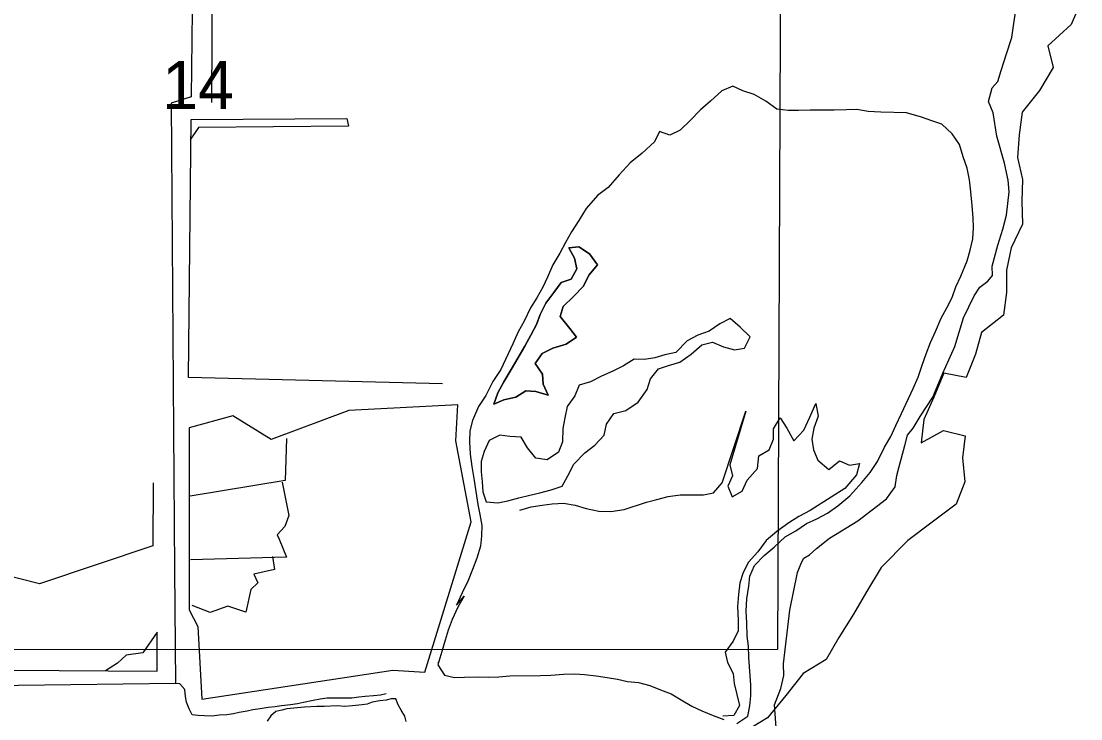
# Model space of a CAD drawing. Extents: x 0 to 34, y 0 to 22.
# Drawn here: x 2.4682 to 2.9274, y 16.9144 to 17.2169 of the extents above; entities that cross this region are included whole.
import ezdxf

# ---------------------------------------------------------------- set-up
doc = ezdxf.new("R2010")
doc.units = 0
for name, color, linetype in [('GM_X_Corporation', 7, 'Continuous'), ('GM_X_Major_Lake', 7, 'Continuous'), ('GM_X_Minor_River', 7, 'Continuous'), ('GM_X_Section_Text', 7, 'Continuous')]:
    doc.layers.add(name, color=color, linetype=linetype)

msp = doc.modelspace()

# ---------------------------------------------------------------- linework, layer by layer
at = {"layer": 'GM_X_Corporation'}
msp.add_lwpolyline([(2.79816, 17.44485), (2.79596, 16.94452), (2.2924, 16.94427), (2.29652, 17.45028)], close=True, dxfattribs=at)
msp.add_lwpolyline([(2.79568, 16.90675), (2.79458, 16.92051), (2.79742, 16.92758), (2.79871, 16.93317), (2.79853, 16.93822), (2.80128, 16.96161), (2.80467, 16.97785), (2.80641, 16.98226), (2.80733, 16.98409), (2.80981, 16.98556), (2.81284, 16.98822), (2.81852, 16.99281), (2.83073, 17.00033), (2.84312, 17.00987), (2.84697, 17.01501), (2.84761, 17.01987), (2.84853, 17.02327), (2.85119, 17.03299), (2.85229, 17.03749), (2.85468, 17.04052), (2.85779, 17.04547), (2.86319, 17.05389), (2.86755, 17.06434), (2.87275, 17.07593), (2.87651, 17.08823), (2.8811, 17.09777), (2.88358, 17.10153), (2.88706, 17.10419), (2.88917, 17.10667), (2.8889, 17.11071), (2.89137, 17.11988), (2.89358, 17.12676), (2.89523, 17.13282), (2.89633, 17.14291), (2.89596, 17.14805), (2.89431, 17.1553), (2.89101, 17.16713), (2.88935, 17.17713), (2.88743, 17.18209), (2.88899, 17.18805), (2.89146, 17.1908), (2.89293, 17.19548), (2.89523, 17.20282), (2.89743, 17.20979), (2.89954, 17.22383)], dxfattribs=at)
msp.add_lwpolyline([(2.79568, 16.90675), (2.79458, 16.92051), (2.79742, 16.92758), (2.79871, 16.93317), (2.79853, 16.93822), (2.80128, 16.96161), (2.80467, 16.97785), (2.80641, 16.98226), (2.80733, 16.98409), (2.80981, 16.98556), (2.81284, 16.98822), (2.81852, 16.99281), (2.83073, 17.00033), (2.84312, 17.00987), (2.84697, 17.01501), (2.84761, 17.01987), (2.84853, 17.02327), (2.85119, 17.03299), (2.85229, 17.03749), (2.85468, 17.04052), (2.85779, 17.04547), (2.86319, 17.05389), (2.86755, 17.06434), (2.87275, 17.07593), (2.87651, 17.08823), (2.8811, 17.09777), (2.88358, 17.10153), (2.88706, 17.10419), (2.88917, 17.10667), (2.8889, 17.11071), (2.89137, 17.11988), (2.89358, 17.12676), (2.89523, 17.13282), (2.89633, 17.14291), (2.89596, 17.14805), (2.89431, 17.1553), (2.89101, 17.16713), (2.88935, 17.17713), (2.88743, 17.18209), (2.88899, 17.18805), (2.89146, 17.1908), (2.89293, 17.19548), (2.89523, 17.20282), (2.89743, 17.20979), (2.89954, 17.22383)], dxfattribs=at)
at = {"layer": 'GM_X_Major_Lake'}
msp.add_lwpolyline([(2.92737, 17.22514), (2.9232, 17.21544), (2.91314, 17.20631), (2.91542, 17.19681), (2.90954, 17.18692), (2.90195, 17.17742), (2.90062, 17.16772), (2.89987, 17.15784), (2.90215, 17.14833), (2.90177, 17.13883), (2.90215, 17.12894), (2.89722, 17.11868), (2.89513, 17.10898), (2.89513, 17.09929), (2.89381, 17.0894), (2.88432, 17.08199), (2.88167, 17.07248), (2.87768, 17.0624), (2.86801, 17.0643), (2.86364, 17.05385), (2.85928, 17.04415), (2.85814, 17.03408), (2.86782, 17.0394), (2.87731, 17.03712), (2.87617, 17.02762), (2.87712, 17.01716), (2.87333, 17.00746), (2.86289, 16.99967), (2.85246, 16.99168), (2.84089, 16.98009), (2.83444, 16.96944), (2.82894, 16.95974), (2.82249, 16.94967), (2.81699, 16.94016), (2.80712, 16.93407), (2.79954, 16.92457), (2.79157, 16.91487), (2.7817, 16.90879)], dxfattribs=at)
at = {"layer": 'GM_X_Minor_River'}
msp.add_line((2.66967, 17.00848), (2.6748, 17.00813), dxfattribs=at)
for points in [[(2.54284, 17.27129), (2.54196, 17.18406), (2.53325, 17.18136), (2.53467, 16.97896), (2.53511, 16.92974), (2.44419, 16.92855)], [(2.66432, 17.23747), (2.55098, 17.23864), (2.55071, 17.18163)], [(2.82722, 17.01113), (2.8325, 17.01685), (2.83609, 17.02124), (2.83929, 17.02601), (2.8423, 17.03229), (2.84512, 17.03687), (2.84718, 17.04163), (2.84963, 17.04677), (2.85169, 17.05115), (2.85469, 17.05763), (2.85695, 17.06258), (2.85863, 17.06772), (2.86031, 17.07267), (2.86219, 17.07762), (2.86444, 17.08238), (2.86688, 17.08809), (2.86932, 17.09267), (2.87158, 17.09705), (2.87326, 17.10181), (2.87533, 17.10638), (2.87814, 17.11304), (2.87944, 17.11761), (2.88056, 17.12256), (2.88091, 17.12731), (2.8807, 17.13168), (2.88029, 17.137), (2.87969, 17.14289), (2.8791, 17.14821), (2.87812, 17.15314), (2.87639, 17.15808), (2.87484, 17.16339), (2.87159, 17.16813), (2.8672, 17.17229), (2.86283, 17.17379), (2.85827, 17.17529), (2.8518, 17.17716), (2.84079, 17.17748), (2.83528, 17.17784), (2.83034, 17.17858), (2.82579, 17.17855), (2.82048, 17.17834), (2.81003, 17.17829), (2.8051, 17.17827), (2.80054, 17.17825), (2.79561, 17.17879), (2.79084, 17.18219), (2.78589, 17.18521), (2.78095, 17.18671), (2.77657, 17.18877), (2.77184, 17.18666), (2.76692, 17.18227), (2.76258, 17.17845), (2.75804, 17.17386), (2.7537, 17.16966), (2.74934, 17.16755), (2.74478, 17.16905), (2.74271, 17.16467), (2.73724, 17.1597), (2.73213, 17.1555), (2.72741, 17.15034), (2.72251, 17.14481), (2.71797, 17.14137), (2.71306, 17.13564), (2.70986, 17.1305), (2.70666, 17.12554), (2.70402, 17.12096), (2.70158, 17.11639), (2.69857, 17.11125), (2.69632, 17.10591), (2.69425, 17.10153), (2.69162, 17.09696), (2.68898, 17.09258), (2.68617, 17.08686), (2.68353, 17.08229), (2.68128, 17.07696), (2.67602, 17.06591), (2.67263, 17.06076), (2.66963, 17.05466), (2.66642, 17.0499), (2.6638, 17.0438), (2.66268, 17.03924), (2.66252, 17.03449), (2.66273, 17.02917), (2.66352, 17.02385), (2.6645, 17.01777), (2.66528, 17.01302), (2.66607, 17.00733), (2.66704, 17.00296), (2.66783, 16.99821), (2.66766, 16.99365), (2.6673, 16.98928), (2.66562, 16.98414), (2.66375, 16.97919), (2.66188, 16.97443), (2.65925, 16.96909), (2.6568, 16.96376), (2.6602, 16.96758)], [(2.65081, 17.05971), (2.54069, 17.06242), (2.54182, 17.17436), (2.6094, 17.17468), (2.60999, 17.17145), (2.54507, 17.17077), (2.54149, 17.16543)], [(2.70599, 17.08363), (2.70879, 17.07994), (2.70444, 17.07687), (2.69856, 17.07514), (2.69402, 17.07283), (2.69101, 17.06845), (2.69407, 17.0639), (2.69447, 17.05953), (2.69658, 17.05479), (2.69126, 17.05629), (2.68689, 17.05665), (2.68254, 17.05396), (2.67742, 17.0528), (2.67306, 17.05088), (2.67475, 17.05583), (2.67738, 17.06059), (2.68058, 17.06593), (2.6834, 17.07088), (2.68641, 17.07603), (2.68904, 17.08079), (2.69149, 17.08537), (2.69317, 17.08975), (2.69562, 17.0947), (2.69901, 17.09928), (2.70221, 17.10366), (2.70657, 17.10501), (2.70902, 17.10959), (2.70804, 17.11414), (2.70555, 17.11869), (2.70992, 17.11909), (2.71449, 17.11607), (2.71793, 17.11134), (2.71416, 17.10676), (2.7119, 17.102), (2.70756, 17.09761), (2.70303, 17.09321), (2.70172, 17.08884), (2.70599, 17.08363)], [(2.70599, 17.08363), (2.70172, 17.08884), (2.70303, 17.09321), (2.70756, 17.09761), (2.7119, 17.102), (2.71416, 17.10676), (2.71793, 17.11134), (2.71449, 17.11607), (2.70992, 17.11909), (2.70555, 17.11869), (2.70804, 17.11414), (2.70902, 17.10959), (2.70657, 17.10501), (2.70221, 17.10366), (2.69901, 17.09928), (2.69562, 17.0947), (2.69317, 17.08975), (2.69149, 17.08537), (2.68904, 17.08079), (2.68641, 17.07603)], [(2.6748, 17.00813), (2.67916, 17.00891), (2.6839, 17.01026), (2.68864, 17.01142), (2.693, 17.01239), (2.69793, 17.01375), (2.70267, 17.01529), (2.70511, 17.01986), (2.70775, 17.02482), (2.71247, 17.02978), (2.71681, 17.03303), (2.72078, 17.03742), (2.72189, 17.04218), (2.7251, 17.04675), (2.73022, 17.04811), (2.73551, 17.05174), (2.73947, 17.05728), (2.74097, 17.06184), (2.74436, 17.06623), (2.74872, 17.06758), (2.75365, 17.06913), (2.75856, 17.07257), (2.7631, 17.07658), (2.76784, 17.07774), (2.77259, 17.07568), (2.77735, 17.07437), (2.78171, 17.07515), (2.78415, 17.0801), (2.77977, 17.08426), (2.77538, 17.08804), (2.77103, 17.08574), (2.7663, 17.08249), (2.76137, 17.08075), (2.75683, 17.07826), (2.75192, 17.0733), (2.74718, 17.07232), (2.74282, 17.07098), (2.73826, 17.07019), (2.7339, 17.07036), (2.72917, 17.06749), (2.72462, 17.06519), (2.7197, 17.06307), (2.71496, 17.06058), (2.71004, 17.05904), (2.70816, 17.05447), (2.70477, 17.04989), (2.70384, 17.04494), (2.70292, 17.04038), (2.70276, 17.03449), (2.70107, 17.03011), (2.69616, 17.02666), (2.69122, 17.0274), (2.68759, 17.03194), (2.68491, 17.03649), (2.67997, 17.03685), (2.6756, 17.0374), (2.67105, 17.0351), (2.6688, 17.03033), (2.66749, 17.02596), (2.66752, 17.02159), (2.66792, 17.01722), (2.66832, 17.01285), (2.66967, 17.00848)], [(2.68641, 17.07603), (2.6834, 17.07088), (2.68058, 17.06593), (2.67738, 17.06059), (2.67475, 17.05583), (2.67306, 17.05088), (2.67742, 17.0528), (2.68254, 17.05396), (2.68689, 17.05665), (2.69126, 17.05629), (2.69658, 17.05479), (2.69447, 17.05953), (2.69407, 17.0639), (2.69101, 17.06845), (2.69402, 17.07283), (2.69856, 17.07514), (2.70444, 17.07687), (2.70879, 17.07994), (2.70599, 17.08363)], [(2.6431, 16.93462), (2.66326, 16.9999), (2.65663, 17.03503), (2.6575, 17.05062), (2.61024, 17.04811), (2.57652, 17.0356), (2.55995, 17.04579), (2.54099, 17.04056), (2.54102, 16.96169), (2.54485, 16.95449), (2.54653, 16.92295), (2.62923, 16.9355), (2.6431, 16.93462)], [(2.6431, 16.93462), (2.66326, 16.9999), (2.65663, 17.03503), (2.6575, 17.05062), (2.61024, 17.04811), (2.57652, 17.0356), (2.55995, 17.04579)], [(2.68431, 17.00494), (2.68924, 17.00629), (2.69398, 17.00708), (2.69834, 17.00767), (2.70328, 17.00788), (2.70822, 17.00714), (2.71297, 17.00565), (2.71848, 17.00453), (2.7238, 17.00437), (2.72949, 17.00515), (2.73915, 17.00843), (2.7437, 17.00959), (2.74863, 17.01076), (2.75375, 17.01154), (2.76381, 17.01159), (2.76818, 17.01237), (2.77195, 17.01676), (2.78216, 17.04781), (2.77533, 17.02457), (2.77649, 17.01982), (2.77442, 17.01525), (2.77635, 17.0107), (2.7807, 17.01319), (2.78276, 17.01795), (2.78729, 17.02291), (2.78784, 17.02843), (2.79238, 17.03111), (2.79425, 17.03568), (2.79423, 17.04024), (2.79705, 17.045), (2.79992, 17.04046), (2.80299, 17.03496), (2.80733, 17.03954), (2.80996, 17.04525), (2.81259, 17.05116), (2.81356, 17.04565), (2.81169, 17.04051), (2.81077, 17.03576), (2.81155, 17.03101), (2.81347, 17.02665), (2.81824, 17.02249), (2.82277, 17.02631), (2.82715, 17.02443), (2.83151, 17.02521), (2.83021, 17.02026), (2.82511, 17.01435), (2.81925, 17.01052), (2.81017, 17.00477), (2.80524, 17.00209), (2.80089, 16.99941), (2.7956, 16.99558), (2.79106, 16.99176), (2.78748, 16.9868), (2.78333, 16.98241), (2.78107, 16.97784), (2.77957, 16.97346), (2.77903, 16.96833), (2.77868, 16.9632), (2.7789, 16.95711), (2.77892, 16.95255), (2.77667, 16.94817), (2.77327, 16.9434), (2.77425, 16.93885), (2.77674, 16.93411), (2.77714, 16.92974), (2.77947, 16.92025), (2.77702, 16.91586), (2.77228, 16.91565)], [(2.55995, 17.04579), (2.54099, 17.04056), (2.54102, 16.96169), (2.54485, 16.95449), (2.54653, 16.92295), (2.62923, 16.9355), (2.6431, 16.93462)], [(2.58316, 17.03601), (2.58268, 17.01777), (2.54152, 17.01092)], [(2.52536, 17.01673), (2.52531, 16.98937), (2.47623, 16.97298), (2.44315, 16.98138), (2.4166, 16.97707), (2.41545, 16.9421), (2.42099, 16.93585), (2.52711, 16.93502), (2.52721, 16.95194), (2.52099, 16.94297), (2.51379, 16.94199), (2.51001, 16.93855), (2.50471, 16.9353)], [(2.58136, 17.017), (2.58428, 17.00257), (2.58241, 16.99781), (2.5792, 16.99418), (2.57997, 16.99229), (2.58323, 16.98451), (2.54167, 16.98336)], [(2.77837, 16.91245), (2.7831, 16.91551), (2.78402, 16.92008), (2.78438, 16.92445), (2.78436, 16.9292), (2.78354, 16.94098), (2.78332, 16.94592), (2.78273, 16.95029), (2.7827, 16.95599), (2.7823, 16.96112), (2.78265, 16.96645), (2.78357, 16.97196), (2.78393, 16.97633), (2.78599, 16.98091), (2.79014, 16.9853), (2.79449, 16.98893), (2.79922, 16.99332), (2.80395, 16.996), (2.80849, 16.99907), (2.81303, 17.00118), (2.81757, 17.00367), (2.82212, 17.00673), (2.82722, 17.01113)], [(2.57716, 16.98486), (2.57795, 16.97916), (2.56903, 16.97722), (2.57076, 16.97343), (2.56774, 16.97056), (2.56551, 16.96067), (2.55772, 16.96329), (2.55014, 16.9606), (2.54234, 16.9636)], [(2.6602, 16.96758), (2.65738, 16.96281), (2.65494, 16.95748), (2.65325, 16.95291), (2.65195, 16.94853), (2.65045, 16.94359), (2.64878, 16.93788), (2.65164, 16.93333), (2.65602, 16.9324), (2.66038, 16.93242), (2.66627, 16.93264), (2.67082, 16.93247), (2.67519, 16.93268), (2.67993, 16.93308), (2.69322, 16.93314), (2.69777, 16.93336), (2.70328, 16.93376), (2.70802, 16.93397), (2.71239, 16.93361), (2.71733, 16.93307), (2.72208, 16.93233), (2.72664, 16.93159), (2.73101, 16.93066), (2.73576, 16.93011), (2.7407, 16.92881), (2.74527, 16.92693), (2.74983, 16.92524), (2.75421, 16.9226), (2.75878, 16.91996), (2.76316, 16.91789), (2.7681, 16.91582), (2.77267, 16.91413)], [(2.64896, 16.93864), (2.64898, 16.93888)], [(2.62644, 16.92523), (2.62398, 16.92464), (2.62094, 16.92444), (2.61733, 16.92404), (2.61449, 16.92384), (2.61145, 16.92345), (2.60082, 16.92339), (2.59779, 16.923), (2.59475, 16.92242), (2.59058, 16.92145), (2.58793, 16.92086), (2.58489, 16.92047), (2.5811, 16.92007), (2.57825, 16.91968), (2.57522, 16.91928), (2.5718, 16.9187), (2.56858, 16.9183), (2.56611, 16.91772), (2.5627, 16.91713), (2.56023, 16.91655), (2.55739, 16.91616), (2.55397, 16.91595), (2.55094, 16.91556), (2.54771, 16.91573), (2.54486, 16.91591), (2.54239, 16.91609), (2.54105, 16.91874), (2.5399, 16.92159), (2.5395, 16.92406), (2.53911, 16.92709), (2.53701, 16.92956), (2.53511, 16.92974)], [(2.63504, 16.91329), (2.63446, 16.91557), (2.63293, 16.91823), (2.63159, 16.9205), (2.63063, 16.92316), (2.62854, 16.92315), (2.62645, 16.92257), (2.62361, 16.92217), (2.62038, 16.92159), (2.61811, 16.92082), (2.61602, 16.92043), (2.61185, 16.92003), (2.60843, 16.91982), (2.60521, 16.92), (2.59951, 16.91978), (2.59629, 16.91976), (2.59097, 16.91955), (2.58338, 16.91875), (2.58111, 16.91817), (2.57864, 16.91759), (2.57637, 16.91568), (2.57487, 16.91339)]]:
    msp.add_lwpolyline(points, dxfattribs=at)

# ---------------------------------------------------------------- texts
at = {"layer": 'GM_X_Section_Text'}
msp.add_text('14', height=0.020928, rotation=0, dxfattribs=at).set_placement((2.52934, 17.17881))

doc.saveas('drawing.dxf')
